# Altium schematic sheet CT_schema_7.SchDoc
size 372 x 335 mm
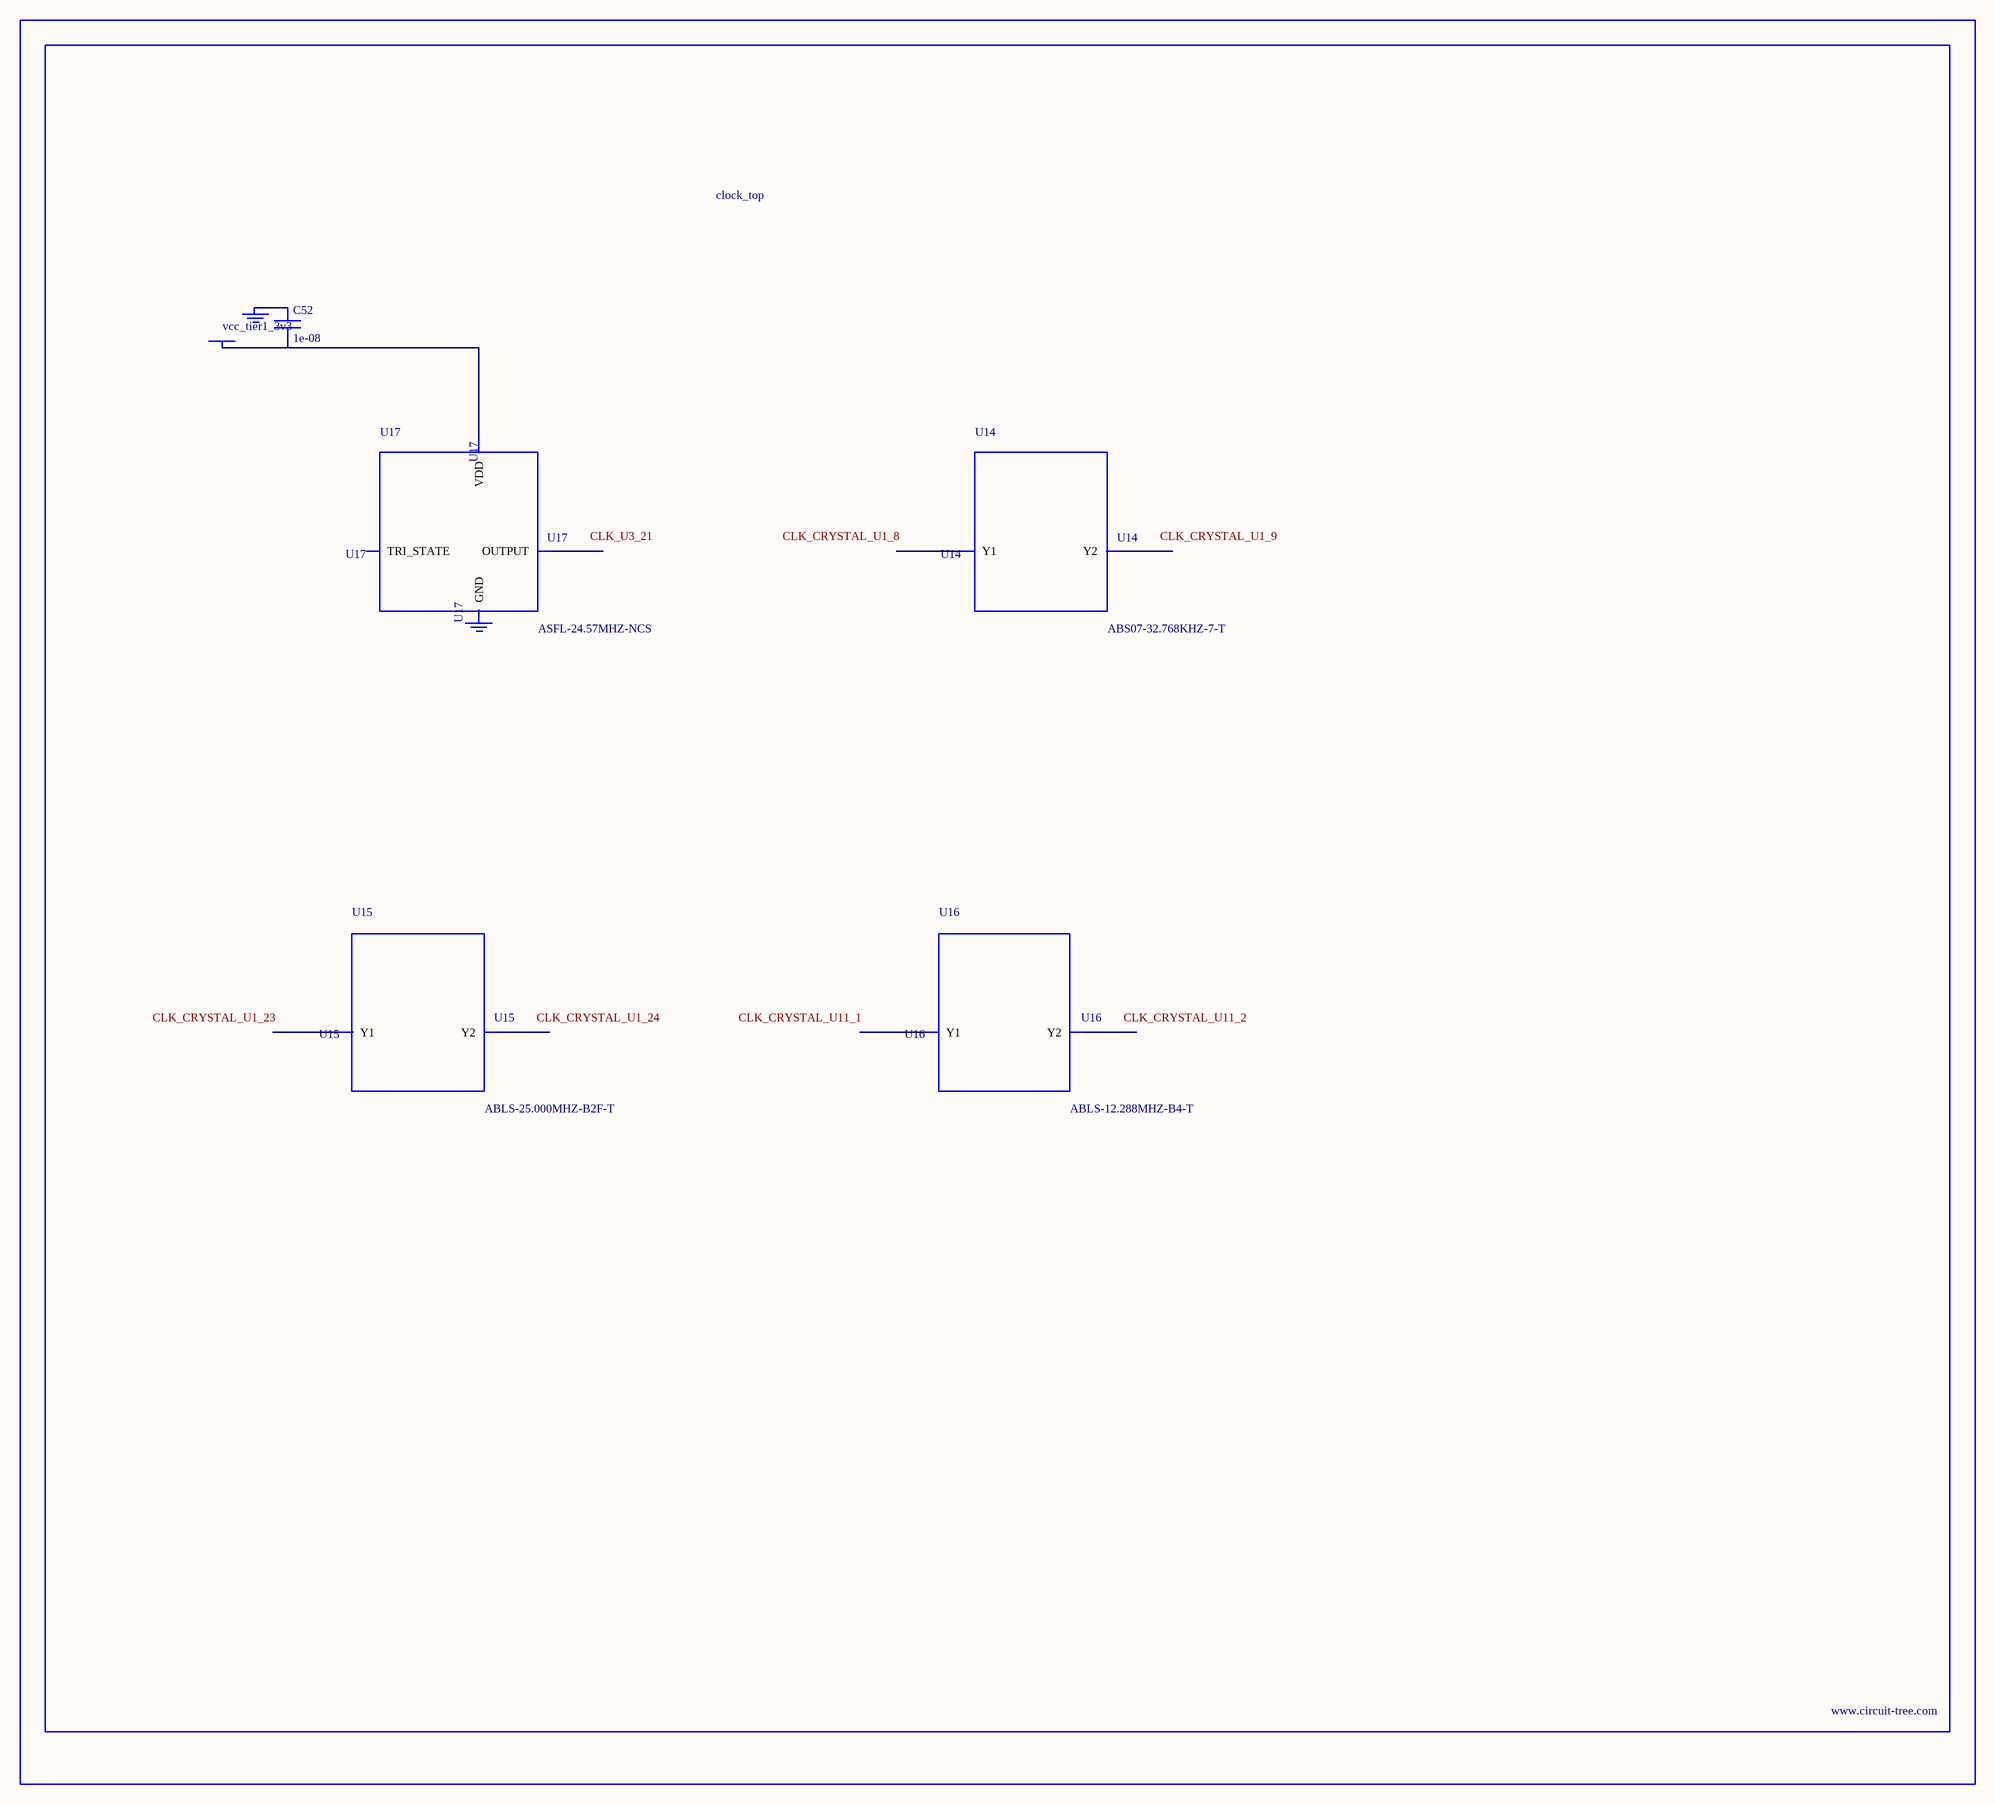
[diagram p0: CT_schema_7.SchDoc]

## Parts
BORDER6  (no value)
C52  1e-08  [C0402]
GND_INSTANCE_6_0  (no value)
GND_INSTANCE_6_1  (no value)
POWER_INSTANCE_6_0  vcc_tier1_3v3
U14  ABS07-32.768KHZ-7-T  [ABS07-32.768KHZ-7-T]
U15  ABLS-25.000MHZ-B2F-T  [ABLS-25.000MHZ-B2F-T]
U16  ABLS-12.288MHZ-B4-T  [ABLS-12.288MHZ-B4-T]
U17  ASFL-24.57MHZ-NCS  [ASFL1]

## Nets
NetC52_1: C52.1 GND_INSTANCE_6_0.0(GND)
NetC52_2: C52.2 POWER_INSTANCE_6_0.0(PWR) U17.4(VDD)

Not connected (* = marked no-connect by the designer): GND_INSTANCE_6_1 0(GND); U14 1(Y1) 2(Y2); U15 1(Y1) 2(Y2); U16 1(Y1) 2(Y2); U17 1(TRI_STATE) 2(GND) 3(OUTPUT)

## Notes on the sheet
- Labels drawn without touching a wire or pin: CLK_CRYSTAL_U1_8, CLK_CRYSTAL_U1_9, CLK_CRYSTAL_U1_23, CLK_CRYSTAL_U1_24, CLK_CRYSTAL_U11_1, CLK_CRYSTAL_U11_2, CLK_U3_21

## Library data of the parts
BORDER6 = BORDER_PAGE6
C52 = C0402C103K3RAC
GND_INSTANCE_6_0 GND_INSTANCE_6_1 = GND
POWER_INSTANCE_6_0 = PWR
